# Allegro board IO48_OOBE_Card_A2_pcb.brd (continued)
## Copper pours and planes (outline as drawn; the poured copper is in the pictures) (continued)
GND on BOTTOM (solid shape): 8.18,85.04 8.18,80.34 9.06,79.45 9.06,78.69 7.79,78.69 7.54,78.95 7.03,78.95 6.4,78.31 6.4,77.29 6.14,77.04 5.76,77.04 5.51,77.29 5.51,80.75 5.97,80.75 5.97,80.69 5.97,80.64 5.99,80.58 6.01,80.53 6.04,80.47 6.08,80.43 6.12,80.39 6.17,80.35 6.22,80.33 6.28,80.31 6.34,80.3 6.4,80.29 6.46,80.3 6.51,80.31 6.57,80.33 6.62,80.35 6.67,80.39 6.71,80.43 6.75,80.47 6.78,80.53 6.8,80.58 6.82,80.64 6.83,80.69 6.83,80.75 6.82,80.81 6.8,80.87 6.78,80.92 6.75,80.97 6.71,81.02 6.67,81.06 6.62,81.09 6.57,81.12 6.51,81.14 6.46,81.15 6.4,81.16 6.34,81.15 6.28,81.14 6.22,81.12 6.17,81.09 6.12,81.06 6.08,81.02 6.04,80.97 6.01,80.92 5.99,80.87 5.97,80.81 5.97,80.75 5.51,80.75 5.51,85.04 5.76,85.3 7.92,85.3
GND on BOTTOM (solid shape): outline of 802 points within 13.64,59.13 17.95,84.66
GND on L2_GND (solid shape): outline of 18844 points within 5.51,49.23 80.69,93.93
GND on L5_GND (solid shape): outline of 18844 points within 5.51,49.23 80.69,93.93
GND on L7_GND (solid shape): outline of 18844 points within 5.51,49.23 80.69,93.93
VCC_3.3V on TOP (solid shape): 23.54,58.37 23.29,58.12 22.14,58.12 21.26,57.23 21.26,55.2 21,54.94 19.86,54.94 19.61,55.2 19.61,59.77 19.99,60.15 23.54,60.15
VCC_3.3V on TOP (solid shape): 50.13,86.96 50.54,86.96 50.79,87.2 51.16,87.2 51.4,86.96 52.83,86.96 53.09,86.69 57.07,86.69 57.2,86.57 57.96,86.57 57.96,85.68 57.45,85.17 57.45,83.77 57.2,83.52 54.15,83.52 53.9,83.26 52.12,83.26 52.12,85.17 51.74,85.55 49.96,85.55 49.45,86.06 49.45,87.07 49.58,87.2 49.89,87.2
VCC_3.3V on BOTTOM (solid shape): 51.08,58.07 51.08,56.34 49.58,54.84 48.87,54.84 48.69,55.02 48.69,55.88 49.7,56.9 49.7,58.24 50.9,58.24
VCC_3.3V on L3_SIG (solid shape): outline of 488 points within 5.89,54.56 21.26,81.23
VCC_3.3V on L4_PWR (solid shape): outline of 6386 points within 7.72,50.24 76.88,91.72
VCC_5V on TOP (solid shape): 39.24,66.39 39.53,66.39 39.67,66.25 39.67,65.17 39.48,64.98 37.51,64.98 37.26,65.23 37.26,66.58 39.05,66.58
VCC_5V on TOP (solid shape): 46.32,86.96 46.73,86.96 46.98,87.2 47.29,87.2 47.42,87.07 47.42,85.8 46.78,85.17 45.64,85.17 45.26,84.79 45.26,83.26 45.64,82.88 45.89,82.88 46.15,82.63 46.15,81.49 45.77,81.1 43.73,81.1 42.34,82.5 42.34,86.44 42.86,86.96 45.46,86.96 45.71,87.2 46.08,87.2
VCC_5V on BOTTOM (solid shape): 39.75,66.35 39.75,65.26 39.21,64.72 35.99,64.72 35.99,65.69 37.21,65.69 38.08,66.56 39.53,66.56
VCC_5V on L6_SIG (solid shape): outline of 501 points within 33.96,64.47 46,82.82
VCC_12V on BOTTOM (solid shape): 19.73,64.24 19.73,63.45 19.61,63.32 17.06,63.32 16.94,63.45 16.94,64.24 17.06,64.37 19.61,64.37
VCC_12V on BOTTOM (solid shape): 11.98,86.06 11.98,81.87 13.51,80.34 13.51,78.79 12.02,78.79 11.72,79.1 10.45,79.1 10.04,78.69 9.57,78.69 9.57,79.71 9.06,80.22 9.06,86.06 9.45,86.44 11.6,86.44
VCC_12V on BOTTOM (solid shape): outline of 143 points within 43.23,86.18 51.99,90.38
VCC_12V on L4_PWR (solid shape): outline of 2401 points within 8.94,84.53 51.99,91.65
VCC_12V on L6_SIG (solid shape): outline of 2142 points within 15.54,58.24 51.99,90.88
VCCIO_HPS on BOTTOM (solid shape): 13.38,62.18 12.49,61.29 10.08,61.29 8.68,62.69 8.68,64.21 11.48,64.21 11.63,64.37 13.38,64.37
VCCIO_HPS on BOTTOM (solid shape): 51.61,64.98 51.61,64.21 51.35,63.96 50.72,63.96 49.83,64.85 48.94,64.85 48.81,64.98 48.81,65.86 50.72,65.86
VCCIO_HPS on BOTTOM (solid shape): 44.88,80.22 44.88,78.56 43.61,78.56 43.35,78.31 43.35,77.55 43.1,77.29 42.59,77.29 42.21,77.68 42.21,79.96 42.85,80.6 44.5,80.6
VCCIO_HPS on BOTTOM (solid shape): 33.57,58.8 33.57,58.09 33.98,57.69 35.05,57.69 35.28,57.46 35.28,56.64 34.97,56.34 33.52,56.34 32.05,57.81 32.05,59.13 33.24,59.13
VCCIO_HPS on BOTTOM (solid shape): 22.78,80.72 22.02,79.96 22.02,79.2 21.38,79.2 20.75,78.56 20.24,78.57 20.01,78.79 18.21,78.79 18.21,79.58 18.75,80.12 19.55,80.12 19.55,80.06 19.56,80 19.58,79.94 19.6,79.89 19.63,79.84 19.67,79.79 19.71,79.75 19.76,79.72 19.81,79.69 19.87,79.67 19.93,79.66 19.99,79.66 20.04,79.66 20.1,79.67 20.16,79.69 20.21,79.72 20.26,79.75 20.3,79.79 20.34,79.84 20.37,79.89 20.39,79.94 20.41,80 20.42,80.06 20.42,80.12 20.41,80.18 20.39,80.23 20.37,80.29 20.34,80.34 20.3,80.38 20.26,80.42 20.21,80.46 20.16,80.49 20.1,80.51 20.04,80.52 19.99,80.52 19.93,80.52 19.87,80.51 19.81,80.49 19.76,80.46 19.71,80.42 19.67,80.38 19.63,80.34 19.6,80.29 19.58,80.23 19.56,80.18 19.55,80.12 18.75,80.12 19.1,80.47 19.1,81.74 19.48,82.12 22.78,82.12
VCCIO_HPS on BOTTOM (solid shape): 27.99,64.59 27.99,63.15 27.94,62.94 27.99,62.74 27.99,62.05 27.48,62.05 27.48,62.69 27.61,62.82 27.61,63.32 27.35,63.58 26.84,63.58 26.59,63.32 26.59,62.82 26.72,62.69 26.72,62.05 26.21,62.05 26.21,62.69 26.34,62.82 26.34,63.32 26.08,63.58 25.57,63.58 25.32,63.32 25.32,62.82 25.45,62.69 25.45,62.05 24.94,62.05 24.94,62.69 25.07,62.82 25.07,63.32 24.81,63.58 24.3,63.58 24.05,63.32 24.05,62.82 24.18,62.69 24.18,62.05 23.67,62.05 23.67,62.69 23.8,62.82 23.8,63.32 23.54,63.58 23.03,63.58 22.78,63.32 22.78,62.82 22.91,62.69 22.91,62.05 22.52,62.05 22.52,62.81 22.53,62.82 22.53,63.32 22.27,63.58 21.76,63.58 21.51,63.32 21.51,62.82 21.64,62.69 21.64,62.55 21.74,62.44 21.74,62.07 21.73,62.05 21.31,62.05 21.13,62.23 21.13,64.34 21.89,65.1 27.48,65.1
VCCIO_HPS on L3_SIG (solid shape): outline of 229 points within 18.21,78.69 21.76,92.28
VCCIO_HPS on L4_PWR (solid shape): outline of 13062 points within 7.67,56.34 59.74,84.91
VCCIO_HPS on L6_SIG (solid shape): outline of 423 points within 50.47,64.09 67.48,81.99
ENET_1.2V_DVDDL on BOTTOM (solid shape): 57.32,78.95 56.31,77.93 55.93,77.93 55.67,78.18 55.67,78.69 55.42,78.95 54.66,78.95 54.15,78.44 53.51,78.44 53.51,78.69 54.53,79.71 54.78,79.71 55.67,80.6 55.93,80.6 56.31,80.98 56.31,82.25 57.32,82.25
ENET_1.2V_DVDDL on L6_SIG (solid shape): outline of 95 points within 46.15,70.69 56.69,80.09
ENET_1.8V_DVDDH on BOTTOM (solid shape): 48.94,78.56 48.94,78.06 47.93,77.04 43.86,77.04 43.86,78.06 46.91,78.06 48.05,79.2 48.31,79.2
ENET_1.8V_DVDDH on L6_SIG (solid shape): outline of 912 points within 42.47,70.44 60.12,81.87
ENET_3.3V_AVDDH on L6_SIG (solid shape): outline of 106 points within 48.05,68.53 54.78,70.56
ENET_VDD1.2V on TOP (solid shape): 62.15,86.06 62.4,85.8 62.4,80.6 62.15,80.34 60.75,80.34 60.37,80.72 60.37,85.17 60.24,85.3 60.24,86.57 61.26,86.57 61.32,86.63 61.44,86.63 61.5,86.69 62.15,86.69
ENET_VDD1.2V on BOTTOM (solid shape): 62.28,81.74 62.28,80.6 62.02,80.34 59.86,80.34 59.48,80.72 58.21,80.72 57.83,81.1 57.83,82.2 57.85,82.23 57.88,82.25 61.77,82.25
ENET_VDD1.2V on L6_SIG (solid shape): outline of 475 points within 41.2,66.63 63.93,90.5
FT232R_3V3OUT on L3_SIG (solid shape): outline of 288 points within 70.41,79.45 76.5,87.2
FT232R_VCCIO on L6_SIG (solid shape): outline of 868 points within 64.06,79.71 76.25,91.42
HPS_OSC_CLK_1.8V on BOTTOM (solid shape): 29.26,75.52 28.62,74.88 28.37,75.14 26.59,75.14 26.59,76.02 28.75,76.02
MICRO_USB_PGND on TOP (solid shape): 42.16,49.66 41.73,49.23 35.07,49.23 35.07,50.98 35.15,51.06 39.49,51.06 39.98,51.54 42.16,51.54
MICRO_USB_PGND on TOP (solid shape): 30.65,53.55 30.65,52.28 29.77,51.39 29.77,49.23 27.83,49.23 27.83,50.35 29.77,52.28 29.77,53.42 30.02,53.67 30.53,53.67
MICRO_USB_PGND on BOTTOM (solid shape): 30.65,53.55 30.65,51.54 31.11,51.08 33.88,51.08 34.21,51.41 34.21,53.42 34.46,53.67 34.84,53.67 35.18,53.34 35.18,51.29 35.45,51.01 38.63,51.01 39.49,51.87 42.69,51.87 42.96,51.6 42.96,49.67 42.52,49.23 27.25,49.23 27.25,51.06 27.28,51.08 29.36,51.08 29.77,51.49 29.77,53.42 30.02,53.67 30.53,53.67
MINI_USB_PGND on TOP (solid shape): 80.69,92.15 80.69,89.99 78.66,89.74 78.41,89.99 78.41,92.41 80.44,92.41
MINI_USB_PGND on BOTTOM (solid shape): 80.69,91.77 80.69,79.58 79.04,77.93 77.77,77.93 77.14,78.56 77.14,79.58 77.77,80.22 79.68,80.22 80.18,80.72 80.18,82.4 80.19,82.46 80.18,82.53 80.18,84 80.19,84.06 80.18,84.13 80.18,85.55 79.42,86.31 77.77,86.31 77.14,86.95 77.14,87.84 78.41,89.11 78.41,92.41 80.06,92.41
SD_3.3V on TOP (solid shape): 23.16,54.43 22.91,54.18 22.02,54.18 21.76,54.43 21.76,56.59 22.02,56.85 23.16,56.85
SD_3.3V on TOP (solid shape): 12.87,57.86 12.87,57.48 12.49,57.1 12.49,54.69 11.73,54.69 11.73,57.13 10.79,58.07 10.79,58.28 10.94,58.44 12.3,58.44
SD_3.3V on BOTTOM (solid shape): 8.81,60.15 8.81,59.63 9.18,59.26 10.38,59.26 11.39,58.24 13.38,58.24 13.38,57.86 12.92,57.4 12.39,57.4 12.15,57.17 12.07,57.17 12.01,57.23 12.01,57.23 11.93,57.31 11.4,57.31 10.46,58.24 8.56,58.24 8.39,58.41 8.39,59.17 8.05,59.51 6.65,59.51 6.65,59.77 6.52,59.77 6.52,60.78 8.18,60.78
SD_3.3V on L6_SIG (solid shape): outline of 651 points within 8.18,52.15 22.65,59.74
USB_5V on TOP (solid shape): 32.15,55.86 32.15,54.66 31.29,53.8 31.17,53.8 30.29,54.69 29,54.69 29,56.19 31.82,56.19
USB_5V on TOP (solid shape): 34.97,63.76 35.3,63.43 35.3,62.68 34.71,62.08 33.49,62.08 32.88,62.69 32.88,63.22 33.07,63.41 33.07,65.92 33.73,66.58 34.97,66.58
USB_5V on BOTTOM (solid shape): 36.88,63.15 37.82,63.15 38.32,62.64 38.32,60.33 38.3,60.3 36.93,60.3 36.6,60.63 36.6,61.5 35.99,62.11 33.45,62.11 32.94,62.61 32.94,64.09 35.94,64.09
USB_5V on L6_SIG (solid shape): 35.28,63.32 35.28,62.23 34.97,61.93 34.06,61.93 33.73,61.6 33.71,61.59 33.67,61.6 33.61,61.6 33.55,61.59 33.49,61.57 33.44,61.54 33.39,61.51 33.35,61.47 33.31,61.43 33.27,61.38 33.25,61.32 33.23,61.27 33.22,61.21 33.22,61.15 33.21,61.08 32.89,60.76 32.89,59.57 33.4,59.06 33.4,55.84 31.43,53.88 31.1,53.88 29.69,55.29 29.69,56.57 32.2,56.57 32.2,56.51 32.21,56.46 32.23,56.4 32.25,56.34 32.28,56.29 32.32,56.25 32.36,56.21 32.41,56.17 32.46,56.15 32.52,56.13 32.58,56.11 32.64,56.11 32.69,56.11 32.75,56.13 32.81,56.15 32.86,56.17 32.91,56.21 32.95,56.25 32.99,56.29 33.02,56.34 33.04,56.4 33.06,56.46 33.07,56.51 33.07,56.57 33.06,56.63 33.04,56.69 33.02,56.74 32.99,56.79 32.95,56.84 32.91,56.88 32.86,56.91 32.81,56.94 32.75,56.96 32.69,56.97 32.64,56.98 32.58,56.97 32.52,56.96 32.46,56.94 32.41,56.91 32.36,56.88 32.32,56.84 32.28,56.79 32.25,56.74 32.23,56.69 32.21,56.63 32.2,56.57 29.69,56.57 29.69,60.96 32.3,63.58 35.02,63.58
USB_VBUS on BOTTOM (solid shape): 39.98,59.77 40.15,59.72 40.33,59.75 40.56,59.51 40.56,59.01 40.31,58.75 37.38,58.75 37.38,59.77
USB_VBUS on L6_SIG (solid shape): outline of 101 points within 38.93,57.23 45.26,59.65
USB_VDDIO on BOTTOM (solid shape): 35.99,61.29 35.99,59.9 35.73,59.64 32.05,59.64 32.05,60.61 33.8,60.61 33.82,60.62 33.92,60.62 34.72,61.42 35.86,61.42
USB_VDDIO on L6_SIG (solid shape): outline of 83 points within 33.4,58.46 47.37,65.59

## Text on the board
BOTTOM: 100-0330632-A2
Ref Des/Silkscreen Bottom: 2 | 60 | 1 | 59 | 20 | 10 | 11 | PROPRIETARY NOTICE: | THIS DOCUMENT CONTAINS PROPRIETARY INFORMATION | OF INTEL CORP. NEITHER THE DOCUMENT NOR SAID | PROPRIETARY INFORMATION SHALL BE PUBLISHED, | REPRODUCED, COPIED, DISCLOSED OR USED FOR ANY | PURPOSE OTHER THAN CONSIDERATION OF THIS DOCUMENT | WITHOUT THE EXPRESS WRITTEN PERMISSION OF A DULY | AUTHORIZED REPRESENTATIVE OF INTEL CORPORATION | DWG NO. | 130-0330632-A2 | SIZE | SCALE: 1/1 | D | REV | A2 | CAGE CODE | N/A | SHEET 2 OF 2 | P/N | S/N
Ref Des/Silkscreen Top: HPS I048 OOBE Card | THIS DOCUMENT CONTAINS PROPRIETARY INFORMATION | OF INTEL CORP. NEITHER THE DOCUMENT NOR SAID | PROPRIETARY INFORMATION SHALL BE PUBLISHED, | REPRODUCED, COPIED, DISCLOSED OR USED FOR ANY | PURPOSE OTHER THAN CONSIDERATION OF THIS DOCUMENT | WITHOUT THE EXPRESS WRITTEN PERMISSION OF A DULY | AUTHORIZED REPRESENTATIVE OF INTEL CORPORATION | PROPRIETARY NOTICE: | DASH | PROJECTION | XX-XXX-XXXX | NEXT ASSY | APPLICATION | UNLESS OTHERWISE SPECIFIED: | DIMENSIONS ARE IN INCHES IN | ACCORDANCE WITH ANSI Y14.5. | DRILL TOLERANCES ARE PER 10387 | USED ON | SPEC | FNSH | TOLERANCES: | DEC .XXXX  .002 | DEC .X | DEC .XX   .01 | DEC .XXX  .005 | FRACTIONS | ANGLES    1 | + | - | o | CHKR | RELEASE | DWN | DSGN ENGR | CONTRACT NO. | DWG NO. | PSG Board Design Team | 130-0330632-A2 | XXXXXXXX | 2-March-2018 | REV | SIZE | TITLE | D | SCALE: 1/1 | A2 | DESCRIPTION | CAGE CODE | N/A | REVISIONS | HPS IQ48 OOBE Daughter Card | PCB ASSEMBLY | DATE | SHEET 1 OF 1 | APPROVED | 19 | 8 | 3 | 21 | 23 | SAN JOSE, CA 95134 | 101 INNOVATION DRIVE | (c) 2018 INTEL Corporation | NOTES: UNLESS OTHERWISE SPECIFIED | 8.  INSTALL BAR CODE LABEL APPROX WHERE SHOWN, INCLUDING S/N. | 1.  ASSEMBLY HOUSE TO VISUALLY VERIFY BOARD BEING ASSEMBLED HAS | 2.  BOARDS MUST BE BAKED FOR A DURATION OF 8 HOURS AT 250 DEGREES | FARENHEIT IMMEDIATELY PRIOR TO ASSEMBLY. | 3.  ASSEMBLE BOARD PER IPC-A-610(LATEST REVISION) STANDARD. | 4.  ALL MATERIALS USED MUST BE RoHS COMPLIANT. | 5.  HANDLE MOISTURE SENSITIVE DEVICES(MSD) PER MANUFACTURE'S | CALL OUT ON MSD LABEL.  IF MSD LABEL IS MISSING OR NOT LEGIBLE | 6.  REWORK MUST BE APPROVED BY CUSTOMER BEFORE BEING ACCEPTIBLE | USE IPC-R-700(LATEST REVISION) FOR ALL PCA REWORK APPROVED. | 7.  SQUARE PIN PAD DENOTE PIN 1 OF ICs/CONNECTORS, POSITIVE END | FOR CAPACITORS OR CATHODE END FOR DIODES. | 9.  VENDOR TO KEEP QUALITY CONTROL INK STAMPINGS OFF SIGNAL TRACES | AND PADS EVEN IF COVERED BY SOLDERMASK. | INTEL P/N 100-0330632-A2 IN ETCH ON BOTTOM SIDE. | THEN ALL PLASTIC PACKAGED COMPONENTS ARE TO BE CONSIDERED MSD | LEVEL 6 AND USE EIA/JEP 113-A FOR HANDLING. | PRIMARY SIDE SHOWN
DIMENSION: Note:If etch layer don't have  above impedance track pls ignore | +/-10% | 1OZ | 0.5OZ+Plating | L6 | L3 | L8 | L1 | 6.1 | 5.6 | 5.2/6.8 | 4.4/8.6 | 5.8/7.2 | 4.8/8.2 | 50 | 90 | 100 | L2;L4 | L5;L7 | L7 | L2 | Via  Technic: | Spell Mode: | Bow and Twist Tolerance:<=0.75% | Inspectionstandard: | Compare With IPC File: | (unit:mil)MIN.track :                       MIN.spacing :                 MIN.hole: | Outline Profile: | Fast Print Logo: | Silk Screen Colours: | Dielectric Material: | Soldermask Colours: | Surface Finished: | Finger Chamfer: | 5.5 | / | Hasl Lead Free | Yes | Green | White | Router | Hasl | Required | Spacing | All via (<=0.5mm) must be filled(except open soldermask via) | IPCII | Pressfit holes: The tolerance of                 is+/-0.05mm | Angle | Board Thickness(MM): | Specified Position | IPCIII | 20 | Bridge | Immersion Tin | No | Yellow | Flash Gold | Blue | Open Windows: | 5 | Matte Green | Black | Immersion Gold | Immersion Silver | 30 | GJB362B | V-cut | Only Date Code | None | Layers: | Gold Finger | Other | 45 | 10 | By gerber | Not Appear | Stamp Hole | QJ831B | Osp | Hi-Tg FR4 | 1.6 | 8 | 5.118(mil) | 13.78(mil) | 4.331(mil) | 3.717(mil) | 1.  STACKING (dielectric thickness can be adjusted beween +/-2mil,but don,t less than 3.5mil; | IF inspection is GJB362B or QJ831B then don,t less than 4mil.) | 2.  Control Impedance (track width can be adjusted +/-0.5mil , but don,t less than 4mil.) | ref layer | * | PWR05 | SIG06 | GND07 | GND04 | TOP | GND02 | SIG03 | BOTTOM | PSG Board Design Team | Purchase   Order &  Specification   Sheet | Board Name: | Lead Time: | SSC PN: | PROPRIETARY NOTICE: | THIS DOCUMENT CONTAINS PROPRIETARY INFORMATION | OF INTEL CORP. NEITHER THE DOCUMENT NOR SAID | PROPRIETARY INFORMATION SHALL BE PUBLISHED, | REPRODUCED, COPIED, DISCLOSED OR USED FOR ANY | PURPOSE OTHER THAN CONSIDERATION OF THIS DOCUMENT | WITHOUT THE EXPRESS WRITTEN PERMISSION OF A DULY | AUTHORIZED REPRESENTATIVE OF INTEL CORPORATION | DASH | THIRD ANGLE | PROJECTION | XX-XXX-XXXX | NEXT ASSY | APPLICATION | UNLESS OTHERWISE SPECIFIED: | DIMENSIONS ARE IN INCHES IN | ACCORDANCE WITH ANSI Y14.5. | DRILL TOLERANCES ARE PER 10387 | USED ON | SPEC | FNSH | MATL | EE: | DATE: | March-2-2018 | [c]2018 Intel Corporation | 101 INNOVATION DRIVE | SAN JOSE, CA. 95134 | TOLERANCES: | DESIGNER: | SHEET | DEC .XXXX  .002 | OF 1 | DEC .X | DEC .XX   .01 | DEC .XXX  .005 | FRACTIONS | ANGLES    1 | TITLE | FILM TITLE | + | - | DOCUMENT NUMBER | HPS IO48 OOBE Daughter Card | 140-0330632-A2 | o | CHKR | RELEASE | DWN | DSGN ENGR | CONTRACT NO. | DWG NO. | XXXXXXXX | 2-March-2018 | REV | A2 | SIZE | D | SCALE: 1/1 | CAGE CODE | N/A | DESCRIPTION | REVISIONS | PCB FABRICATION | DATE | SHEET 1 OF 1 | APPROVED | 19 | 3 | 21 | 23 | (c) 2018 INTEL Corporation | SAN JOSE, CA 95134 | (LATEST REVISION). | NOTES UNLESS OTHERWISE SPECIFIED: | 1. PCB VENDOR MUST NOTIFY RESPONSIBLE INTEL PCB CONTACT OF ANY DISCREPANCIES | FOUND BETWEEN FABRICATION DATA AND FABRICATION DRAWING NOTES. | 2. THIS DRAWING IS VIEWED FROM THE PRIMARY OR TOP SIDE OF THE PCB. | 3  FABRICATION OF THIS PCB SHALL BE IN CONFORMANCE WITH THE FOLLOWING | SPECIFICATIONS: IPC-6011 CLASS 2 (GENERIC). | 4. ALL MATERIALS USED MUST BE RoHS COMPLIANT. | 5. FABRICATION OF THIS PCB TO BE ACCEPTABLE TO IPC-A-600 CLASS 2 | 6. ALL DIMENSIONAL LIMITS APPLY AFTER PLATING OR PROCESSING. | 7. TOLERANCES OF DATUM HOLE TO:  BOARD EDGE LOCATIONS +/- 0.010. | DRILLED HOLE LOCATIONS +/- 0.003. | V-SCORE LOCATIONS +/- 0.010 | 8  BASE MATERIAL: Hi-Tg FR4 | 9. FLAME CLASS: UL 94V-0 & MUST MEET REQUIREMENTS OF UL796. | 10. MANUFACTURER MUST BE UL RECOGNIZED TO PRODUCE THIS PRODUCT SUCH THAT | 11  THE FOLLOWING MUST BE MARKED OR ETCHED ON SECONDARY SIDE OF PCB IN AREA | SHOWN: | a)  DATE CODE. | b)  UL RECOGNIZED VENDOR ID, UL TYPE DESIGNATION AND/OR MARKINGS WHICH | REFLECT THE SPECIFIED FLAME CLASS AND MAXIMUM OPERATING TEMPERATURE | RATINGS. | 12. PCB VENDOR TO ENSURE ALL UNCONNECTED (NON-FUNCTIONAL) INTERNAL SIGNAL | LAYER PADS AND VIAS ARE REMOVED. | 13. HOLE/SLOT PLATING = 0.001 MIN. AVERAGE / 0.0008 ABSOLUTE MIN. PLATING. | HOLE/SLOT DIAMETERS ARE SPECIFIED AFTER PLATING (SEE HOLE SCHEDULE). | 14  THESE VIA IN PAD MUST BE VIA FILLED USING NON-CONDUCTIVE | 15. AFTER REVIEWING FABRICATION DATA, PCB VENDOR MUST DISCUSS WHETHER COPPER | THIEVING IS NECESSARY WITH THE RESPONSIBLE INTEL PCB CONTACT.  WHEN | DETERMINED NECESSARY.  A SPACING OF 100 MILS FROM ANY OTHER COPPER FEATURE | ON THE BOARD MUST BE MAINTAINED. | 16. SMEAR REMOVAL SHALL NOT ETCHBACK GREATER THAN 0.001. | 17. FINISHED CONDUCTOR WIDTH NOT TO BE REDUCED MORE THAN 20% OF MINIMUM WIDTH | FROM ARTWORK SUPPLIED. FINISHED CONDUCTOR SPACING NOT TO BE REDUCED MORE | THAN 20% OF MINIMUM SPACING FROM ARTWORK SUPPLIED. | 18. TEAR DROPPING OF TRACE TO PAD JUNCTION IS PERMITTED PROVIDED MINIMUM | METAL-TO-METAL ARTWORK SPACINGS ARE NOT COMPROMISED. | 19  SOLDER MASK IS LIQUID PHOTO IMAGEABLE AND IN ACCORDANCE WITH IPC-SM-840C | CLASS T.  FINISH MUST BE GREEN AND GLOSSY. REGISTRATION TO BE WITHIN | +/- 0.003 OF ITS RESPECTIVE OUTER CIRCUIT LAYERS. VENDOR MAY ADJUST | SOLDERMASK WHEREVER SOLDERMASK PADS ARE THE SAME SIZE (1:1) TO PROVIDE UP | TO .003 MAXIMUM CLEARANCE FROM MASK TO PAD PROVIDED NO ADJACENT COPPER IS | EXPOSED AND NO CONFLICT IS PRODUCED WITH ANY STATED "VIA TENTING/PLUGGING" | REQUIREMENTS. | 20  PCB VENDOR TO ENSURE VIAS ARE SOLDERMASK ENCROACHED ON BOTTOM SIDE OF | PCB, EXCEPT IN AREAS SHOWN DUE TO BOTTOM MOUNT BGA PACKAGES. | 21  PCB FINISH BOTH SIDES TO BE ELECTROLESS NICKEL (Ni) FOLLOWED BY IMMERSION | GOLD (AU) (ENIG) ACCEPTABLE TO IPC-4552. | 22. REMOVE ALL SHARP EDGES AND BURRS 0.003" MAXIMUM. | 23  SILKSCREEN USING WHITE NONCONDUCTIVE INK. NO INK TO APPEAR ON EXPOSED | COPPER SUCH AS PLATED THROUGH HOLE PADS AND SURFACE MOUNT LANDS. INK | ON SOLDER MASK COVERED PADS IS PERMISSIBLE. CLIPPING OF SILKSCREEN | 0.008 MAX. FROM PADS IS PERMITTED. | 24. BOW & TWIST SHALL BE DETERMINED BY PHYSICAL MEASUREMENT AND PERCENTAGE | CALCULATION IN ACCORDANCE WITH IPC-TM-650, METHOD 2.4.22. BOW AND TWIST | MAY NOT EXCEED 0.7% | 25. 100% CONTINUITY AND ISOLATION ELECTRICAL TESTING PER CURRENT IPC TEST | METHODS REQUIRED FOR EVERY PCB. FINAL PCB TEST DATA MUST BE CROSS- | REFERENCED TO IPC-D-356 FILE, NEUTRAL FILE OR NETLIST PROVIDED. | 26. PCB VENDOR TO PROVIDE ONE TEST COUPON AND ONE CROSS SECTION PER LOT WITH | SHIPMENT. | 27. PCB VENDOR TO PROVIDE 2 SOLDER SAMPLES WITH FIRST SHIPMENT. | 28  VENDOR TO KEEP QUALITY CONTROL INK STAMPINGS ON BOTTOM OF PCB IN AREA | SPECIFIED.  STAMPINGS CANNOT BE ON TRACES OR PADS EVEN IF COVERED BY MASK. | 29. DETAILS NOT SPECIFIED ARE AT MANUFACTURER'S OPTION, HOWEVER | FINAL APPROVAL MUST BE OBTAINED. | IT MEETS 130 DEGREES CELSIUS MAXIMUM OPERATING TEMPERATURE (MOT). | EPOXY VIA FILL, PLANARIZED AND PLATED OVER.
User.23: FIGURE | SIZE | 12.0 | 24.0 | 35.0 | 40.0 | 45.0 | 50.0 | 62.0 | 79.0 | 125.0 | 128.0 | 30.0 | 95.0 | 33.461x25.591 | 59.059x32.681 | DRILL CHART: TOP to BOTTOM | ALL UNITS ARE IN MILS | TOLERANCE | +3.0/-3.0 | +2.0/-2.0 | PLATED | NON-PLATED | QTY | 602 | 5 | 17 | 2 | 3
